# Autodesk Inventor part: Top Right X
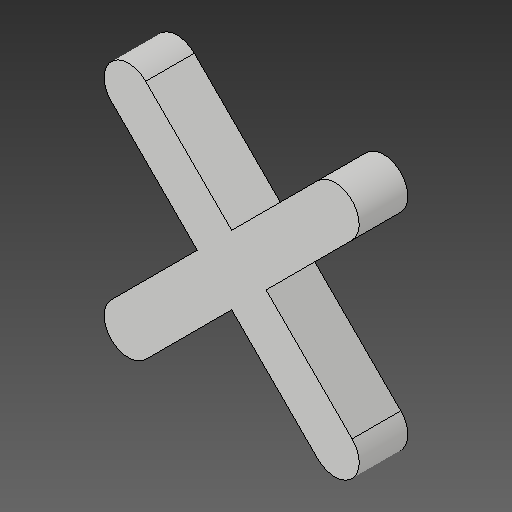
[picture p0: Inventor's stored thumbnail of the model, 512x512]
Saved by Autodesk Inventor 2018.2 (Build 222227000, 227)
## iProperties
Created: 2018-03
Part Number: Top Right X
Material: Generic
Document SubType Name: Modeling
Designer: PeterMaxwell-Stewart
Mass: 1.57135 g
Surface Area: 12.8562 cm^2
Volume: 1.57135 cm^3
Density: 1 g/cm^3
Appearance: Default
Author: PeterMaxwell-Stewart
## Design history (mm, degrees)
derived "O's and X's.ipt"
feature "Top Right X::O's and X's.ipt" dims "d0" = 10
tag "TaggingFeature1"
body "Solid1"
